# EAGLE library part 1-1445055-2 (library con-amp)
Micro MATE-N-LOK Connectors grid 1.5 mm Source: ENG_CD_1445055_A.pdf
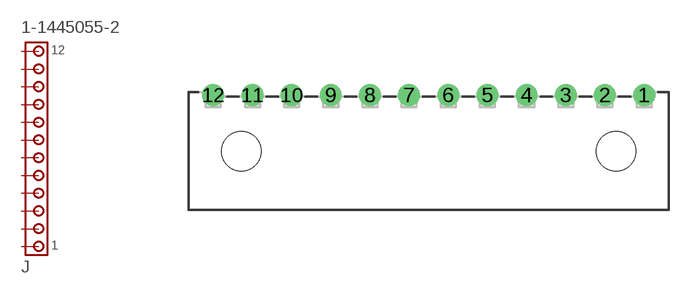
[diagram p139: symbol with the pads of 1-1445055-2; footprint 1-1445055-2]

Designator prefix J

## 1-1445055-2 (MF: TYCO ELECTRONICS; MPN: 1-1445055-2; OC_FARNELL: unknown; OC_NEWARK: 09H5355)  [1-1445055-2]
1  1  pas
2  2  pas
3  3  pas
4  4  pas
5  5  pas
6  6  pas
7  7  pas
8  8  pas
9  9  pas
10  10  pas
11  11  pas
12  12  pas

## Footprint 1-1445055-2 (pad centres in mm)
Micro MATE-N-LOK Connectors grid 1.5 mm Source: ENG_CD_1445055_A.pdf
drill 1 pad 1.676 round: 1 16.5,4.32; 2 13.5,4.32; 3 10.5,4.32; 4 7.5,4.32; 5 4.5,4.32; 6 1.5,4.32; 7 -1.5,4.32; 8 -4.5,4.32; 9 -7.5,4.32; 10 -10.5,4.32; 11 -13.5,4.32; 12 -16.5,4.32
hole 3 at -14.35,0
hole 3 at 14.35,0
